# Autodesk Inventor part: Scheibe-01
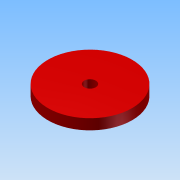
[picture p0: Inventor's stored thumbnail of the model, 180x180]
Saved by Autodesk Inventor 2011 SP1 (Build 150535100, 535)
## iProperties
Created: 2010-12
Part Number: Scheibe-01
Document SubType Name: Modeling
Designer: Udo.Huebner
Density: 1 g/cm^3
Author: Udo.Huebner
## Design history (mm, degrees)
sketch "Skizze1"
  geometry: C1 r 40 at (0, 0); C2 r 5.5 at (0, 0); 1 further point
  constraints: 2 centre point, 2 coincident
  dimensions: "AD" = 80 diameter of C1; "d1" = 11 diameter of C2
extrude "Extrusion1" new body sketch "Skizze1" distance "d2" = 10; taper "d3" = 0 deg
node "Volumenkörper1"
other parameters: "d4" = 0, "d5" = 0
